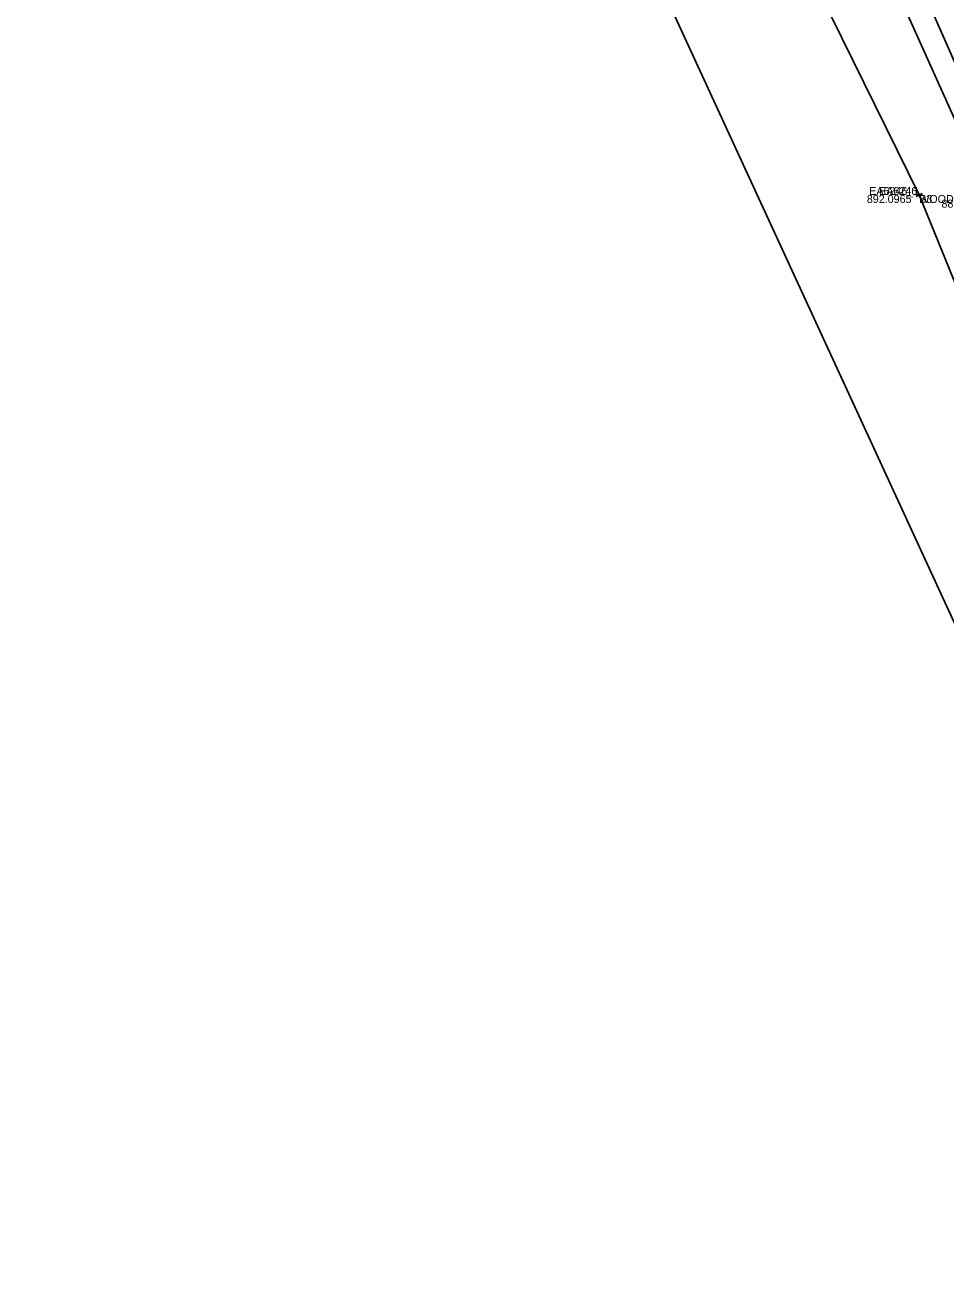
# Model space of a CAD drawing. Extents: x 179044 to 189691, y 286531 to 301257.
# Drawn here: x 180120 to 180258, y 300212.2 to 300401.7 of the extents above; entities that cross this region are included whole.
import ezdxf

# ---------------------------------------------------------------- set-up
doc = ezdxf.new("R2010")
doc.units = 0
for name, color, linetype in [('RD_X_Fence', 7, 'Continuous'), ('SV_X_Break_Lines', 7, 'Continuous'), ('SV_X_Shot_Marker', 7, 'Continuous'), ('SV_X_Text_Comment', 7, 'Continuous'), ('SV_X_Text_Elevation', 7, 'Continuous'), ('SV_X_Text_Name', 7, 'Continuous'), ('VG_X_Tree_Line_Lt', 7, 'Continuous')]:
    doc.layers.add(name, color=color, linetype=linetype)

msp = doc.modelspace()

# ---------------------------------------------------------------- linework, layer by layer
at = {"layer": 'RD_X_Fence'}
msp.add_lwpolyline([(179565.42, 300550.82), (179667.83, 300544.25), (179812.22, 300533.93), (179896.21, 300528.36), (179941.19, 300525.4), (180078.77, 300515.9), (180168.34, 300509.72), (180196.88, 300447.72), (180266.67, 300296.15), (180285.87, 300252.94)], dxfattribs=at)
at = {"layer": 'SV_X_Break_Lines'}
for points in [[(180320.9, 300212.18), (180282.07, 300307.44), (180254.03, 300376.29), (180214.22, 300457.22), (180192.83, 300518.47), (180187, 300524.65), (180178.54, 300551.92), (180167.49, 300556.19), (180133.43, 300560.27), (180078.67, 300564.71), (179988.56, 300564.71), (179881.16, 300565.14), (179774.57, 300564.41), (179665.2, 300563.79), (179565.53, 300563.69)], [(180193.08, 300550.15), (180219.62, 300475.89), (180264.74, 300375.59), (180291.67, 300310.22), (180324.83, 300229.15)], [(180195.86, 300550.95), (180223.23, 300478.01), (180267.79, 300377.03), (180294.71, 300311.68), (180328.37, 300228.86)]]:
    msp.add_lwpolyline(points, dxfattribs=at)
at = {"layer": 'SV_X_Shot_Marker'}
for p, q in [((180253.57, 300376.1), (180254.5, 300376.47)), ((180254.48, 300376.51), (180253.58, 300376.07)), ((180253.81, 300376.73), (180254.25, 300375.84)), ((180254.22, 300375.82), (180253.84, 300376.75)), ((180254.03, 300376.29), (180254.03, 300376.29)), ((180254.03, 300376.29), (180254.03, 300376.29))]:
    msp.add_line(p, q, dxfattribs=at)
at = {"layer": 'VG_X_Tree_Line_Lt'}
msp.add_lwpolyline([(180168.34, 300509.72), (180182.03, 300509.27), (180214.22, 300457.22), (180254.03, 300376.29), (180282.07, 300307.44), (180320.9, 300212.18)], dxfattribs=at)

# ---------------------------------------------------------------- texts
at = {"layer": 'SV_X_Text_Comment'}
for s in ['WOODSR', 'B3']:
    msp.add_text(s, height=1.2, dxfattribs=at).set_placement((180254.03, 300375.09))
at = {"layer": 'SV_X_Text_Elevation'}
for s, p in [('892.0965', (180246.18, 300375.09)), ('892.0965', (180246.18, 300375.09)), ('889.8201', (180257.36, 300374.39))]:
    msp.add_text(s, height=1.2, dxfattribs=at).set_placement(p)
at = {"layer": 'SV_X_Text_Name'}
for s, p in [('EA6246_1', (180246.54, 300376.29)), ('EA6246', (180248.02, 300376.29))]:
    msp.add_text(s, height=1.2, dxfattribs=at).set_placement(p)

doc.saveas('drawing.dxf')
